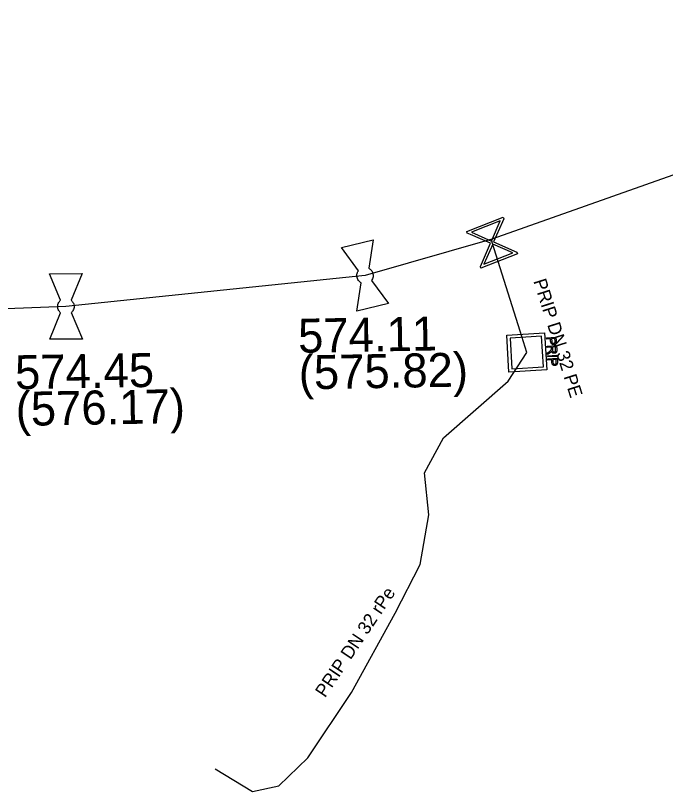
# Model space of a CAD drawing. Extents: x -643544 to -637295, y -1119190 to -1111715.
# Drawn here: x -641861.48 to -641836.62, y -1113654.55 to -1113624.89 of the extents above; entities that cross this region are included whole.
import ezdxf

# ---------------------------------------------------------------- set-up
doc = ezdxf.new("R2010")
doc.units = 0
for name, color, linetype in [('Default', 7, 'Continuous'), ('VP Lomový bod', 7, 'Continuous'), ('VP Lomový bod - popis', 7, 'Continuous'), ('VP Popis přípojky', 7, 'Continuous'), ('VP Přípojka', 7, 'Continuous'), ('VP Řad', 7, 'Continuous'), ('VP Šachta', 7, 'Continuous'), ('VP Šoupě', 7, 'Continuous')]:
    doc.layers.add(name, color=color, linetype=linetype)

msp = doc.modelspace()

# ---------------------------------------------------------------- linework, layer by layer
at = {"layer": 'Default'}
for points in [[(-641848.254, -1113635.109), (-641848.3, -1113635.085), (-641848.337, -1113635.046), (-641848.395, -1113634.982), (-641848.414, -1113634.902), (-641848.433, -1113634.823), (-641848.41, -1113634.742), (-641848.394, -1113634.69), (-641848.363, -1113634.647)], [(-641847.967, -1113634.552), (-641847.92, -1113634.576), (-641847.882, -1113634.616), (-641847.825, -1113634.678), (-641847.806, -1113634.758), (-641847.787, -1113634.837), (-641847.811, -1113634.921), (-641847.825, -1113634.972), (-641847.856, -1113635.014)], [(-641859.754, -1113636.249), (-641859.793, -1113636.215), (-641859.82, -1113636.169), (-641859.862, -1113636.093), (-641859.862, -1113636.011), (-641859.863, -1113635.93), (-641859.822, -1113635.856), (-641859.795, -1113635.808), (-641859.755, -1113635.774)], [(-641859.347, -1113635.772), (-641859.307, -1113635.806), (-641859.28, -1113635.854), (-641859.238, -1113635.927), (-641859.238, -1113636.009), (-641859.237, -1113636.09), (-641859.28, -1113636.166), (-641859.305, -1113636.213), (-641859.345, -1113636.247)], [(-641840.799, -1113637.324), (-641840.797, -1113637.36), (-641840.8, -1113637.379), (-641840.803, -1113637.405), (-641840.814, -1113637.424), (-641840.825, -1113637.443), (-641840.846, -1113637.455), (-641840.868, -1113637.466), (-641840.895, -1113637.468), (-641840.941, -1113637.471), (-641840.974, -1113637.444), (-641841.006, -1113637.417), (-641841.011, -1113637.341)], [(-641840.969, -1113637.339), (-641840.967, -1113637.385), (-641840.949, -1113637.403), (-641840.93, -1113637.421), (-641840.899, -1113637.419), (-641840.877, -1113637.418), (-641840.862, -1113637.406), (-641840.846, -1113637.394), (-641840.843, -1113637.376), (-641840.84, -1113637.363), (-641840.842, -1113637.33)], [(-641841.06, -1113637.734), (-641841.028, -1113637.712), (-641841.012, -1113637.697), (-641840.996, -1113637.683), (-641840.99, -1113637.672), (-641840.984, -1113637.66), (-641840.982, -1113637.649), (-641840.98, -1113637.642), (-641840.981, -1113637.623)], [(-641840.779, -1113637.668), (-641840.776, -1113637.715), (-641840.785, -1113637.741), (-641840.793, -1113637.766), (-641840.816, -1113637.783), (-641840.84, -1113637.799), (-641840.869, -1113637.8), (-641840.908, -1113637.803), (-641840.935, -1113637.78), (-641840.962, -1113637.757), (-641840.972, -1113637.706), (-641840.981, -1113637.725), (-641840.989, -1113637.735), (-641841.006, -1113637.757), (-641841.034, -1113637.777)], [(-641840.938, -1113637.667), (-641840.936, -1113637.7), (-641840.928, -1113637.718), (-641840.921, -1113637.736), (-641840.905, -1113637.744), (-641840.89, -1113637.753), (-641840.872, -1113637.752), (-641840.848, -1113637.75), (-641840.832, -1113637.731), (-641840.817, -1113637.712), (-641840.819, -1113637.671)], [(-641840.754, -1113638.125), (-641840.751, -1113638.16), (-641840.754, -1113638.18), (-641840.757, -1113638.206), (-641840.768, -1113638.225), (-641840.78, -1113638.244), (-641840.801, -1113638.255), (-641840.822, -1113638.267), (-641840.849, -1113638.269), (-641840.895, -1113638.271), (-641840.928, -1113638.245), (-641840.961, -1113638.218), (-641840.965, -1113638.142)], [(-641840.924, -1113638.14), (-641840.921, -1113638.186), (-641840.903, -1113638.204), (-641840.885, -1113638.222), (-641840.853, -1113638.22), (-641840.831, -1113638.219), (-641840.816, -1113638.207), (-641840.801, -1113638.195), (-641840.797, -1113638.176), (-641840.794, -1113638.164), (-641840.796, -1113638.131)]]:
    msp.add_open_spline(points, degree=3, dxfattribs=at)
at = {"layer": 'VP Lomový bod'}
for points in [[(-641848.363, -1113634.647), (-641849.008, -1113633.759), (-641847.792, -1113633.469), (-641847.967, -1113634.552)], [(-641859.755, -1113635.774), (-641860.181, -1113634.763), (-641858.931, -1113634.757), (-641859.347, -1113635.772)], [(-641847.212, -1113635.901), (-641848.428, -1113636.191), (-641848.254, -1113635.109)], [(-641847.856, -1113635.014), (-641847.212, -1113635.901)], [(-641858.919, -1113637.257), (-641860.169, -1113637.263), (-641859.754, -1113636.249)], [(-641859.345, -1113636.247), (-641858.919, -1113637.257)]]:
    msp.add_lwpolyline(points, dxfattribs=at)
at = {"layer": 'VP Přípojka'}
msp.add_lwpolyline([(-641853.84, -1113653.68), (-641852.41, -1113654.55), (-641851.4, -1113654.33), (-641850.3, -1113653.26), (-641848.63, -1113650.77), (-641846.96, -1113647.73), (-641846, -1113645.88), (-641845.67, -1113643.97), (-641845.84, -1113642.37), (-641845.11, -1113641.03), (-641842.64, -1113638.86), (-641841.92, -1113637.77), (-641842.18, -1113636.95), (-641843.25, -1113633.57), (-641843.26, -1113633.44)], dxfattribs=at)
at = {"layer": 'VP Řad'}
msp.add_lwpolyline([(-641818.83, -1113624.89), (-641824.82, -1113627.01), (-641835.08, -1113630.55), (-641843.26, -1113633.44), (-641848.11, -1113634.83), (-641859.55, -1113636.01), (-641870.93, -1113636.46)], dxfattribs=at)
at = {"layer": 'VP Šachta'}
for points in [[(-641841.157, -1113638.433), (-641842.606, -1113638.518), (-641842.689, -1113637.107), (-641841.24, -1113637.022), (-641841.157, -1113638.433)], [(-641841.356, -1113637.15), (-641842.559, -1113637.22), (-641842.49, -1113638.39), (-641841.287, -1113638.32), (-641841.356, -1113637.15)], [(-641841.165, -1113637.211), (-641840.807, -1113637.19), (-641840.799, -1113637.324)], [(-641841.011, -1113637.341), (-641841.016, -1113637.249), (-641841.162, -1113637.257), (-641841.165, -1113637.211)], [(-641840.842, -1113637.33), (-641840.847, -1113637.239), (-641840.975, -1113637.246)], [(-641840.975, -1113637.246), (-641840.969, -1113637.339)], [(-641841.147, -1113637.53), (-641840.788, -1113637.509), (-641840.779, -1113637.668)], [(-641840.981, -1113637.623), (-641840.984, -1113637.569), (-641841.144, -1113637.578), (-641841.147, -1113637.53)], [(-641841.034, -1113637.777), (-641841.128, -1113637.845), (-641841.132, -1113637.785), (-641841.06, -1113637.734)], [(-641840.819, -1113637.671), (-641840.826, -1113637.559), (-641840.944, -1113637.566)], [(-641840.944, -1113637.566), (-641840.938, -1113637.667)], [(-641841.127, -1113637.894), (-641840.768, -1113637.873), (-641840.766, -1113637.919), (-641841.124, -1113637.94), (-641841.127, -1113637.894)], [(-641841.12, -1113638.012), (-641840.761, -1113637.991), (-641840.754, -1113638.125)], [(-641840.965, -1113638.142), (-641840.971, -1113638.05), (-641841.117, -1113638.058), (-641841.12, -1113638.012)], [(-641840.796, -1113638.131), (-641840.801, -1113638.04), (-641840.929, -1113638.047)], [(-641840.929, -1113638.047), (-641840.924, -1113638.14)]]:
    msp.add_lwpolyline(points, dxfattribs=at)
at = {"layer": 'VP Šoupě'}
for points in [[(-641844.222, -1113633.145), (-641842.825, -1113632.598), (-641842.801, -1113632.66), (-641842.856, -1113632.776), (-641843.192, -1113633.546), (-641842.302, -1113633.934), (-641842.278, -1113633.995), (-641843.675, -1113634.542), (-641843.699, -1113634.48), (-641843.308, -1113633.591), (-641844.078, -1113633.255), (-641844.198, -1113633.206), (-641844.222, -1113633.145)], [(-641844.041, -1113633.175), (-641843.273, -1113633.51), (-641842.938, -1113632.743), (-641844.041, -1113633.175)], [(-641842.454, -1113633.963), (-641843.227, -1113633.626), (-641843.563, -1113634.397), (-641842.454, -1113633.963)]]:
    msp.add_lwpolyline(points, dxfattribs=at)

# ---------------------------------------------------------------- texts
at = {"layer": 'VP Lomový bod - popis'}
for s, p in [('574.11', (-641850.659, -1113637.783)), ('574.45', (-641861.484, -1113639.178)), ('(575.82)', (-641850.634, -1113639.183)), ('(576.17)', (-641861.459, -1113640.578))]:
    msp.add_text(s, height=1.3, rotation=1, dxfattribs=at).set_placement(p)
at = {"layer": 'VP Popis přípojky'}
for s, rotation, p in [('PRIP DN 32 PE', 287.5661, (-641841.676, -1113635.039)), ('PRIP DN 32 rPe', 56.1509, (-641849.637, -1113650.992))]:
    msp.add_text(s, height=0.5, rotation=rotation, dxfattribs=at).set_placement(p)

doc.saveas('drawing.dxf')
